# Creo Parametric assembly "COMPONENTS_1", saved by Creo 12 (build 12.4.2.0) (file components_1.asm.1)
Units: Custom; MM, KILOGRAM, SECS

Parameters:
  PTC_WM_ITERATION = "0"
  PTC_WM_VERSION = "-.0"
  PTC_WM_LIFECYCLE_STATE = "In Work"
  PTC_WM_LIFECYCLE = "MO_CADDocument"
  PTC_WM_CREATED_BY = "Maximilian Roepper (Z0017RMS: MO)"
  PTC_WM_CREATED_ON = "18-Sep-26 11:36:42 AM"
  PTC_WM_MODIFIED_BY = "Maximilian Roepper (Z0017RMS: MO)"
  PTC_WM_MODIFIED_ON = "18-Sep-26 11:36:46 AM"
  PDMLINKNUMBER = "PDM000071455169"
  PTC_WM_NUMBER = "PDM000071455169"

Other parameters: WEIGHT, WEIGHT_FACTOR, WEIGHT_ADD, MC_ERRORS, SUPPLIER

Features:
  1. coordinate system
  2. imported feature
  3. component "SD_SLOT_1"
  4. component "PARTS_1"
  5. component "PLS-14_1"

Other named items: DRW_VIEW_ORG, ROUGH-GROB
